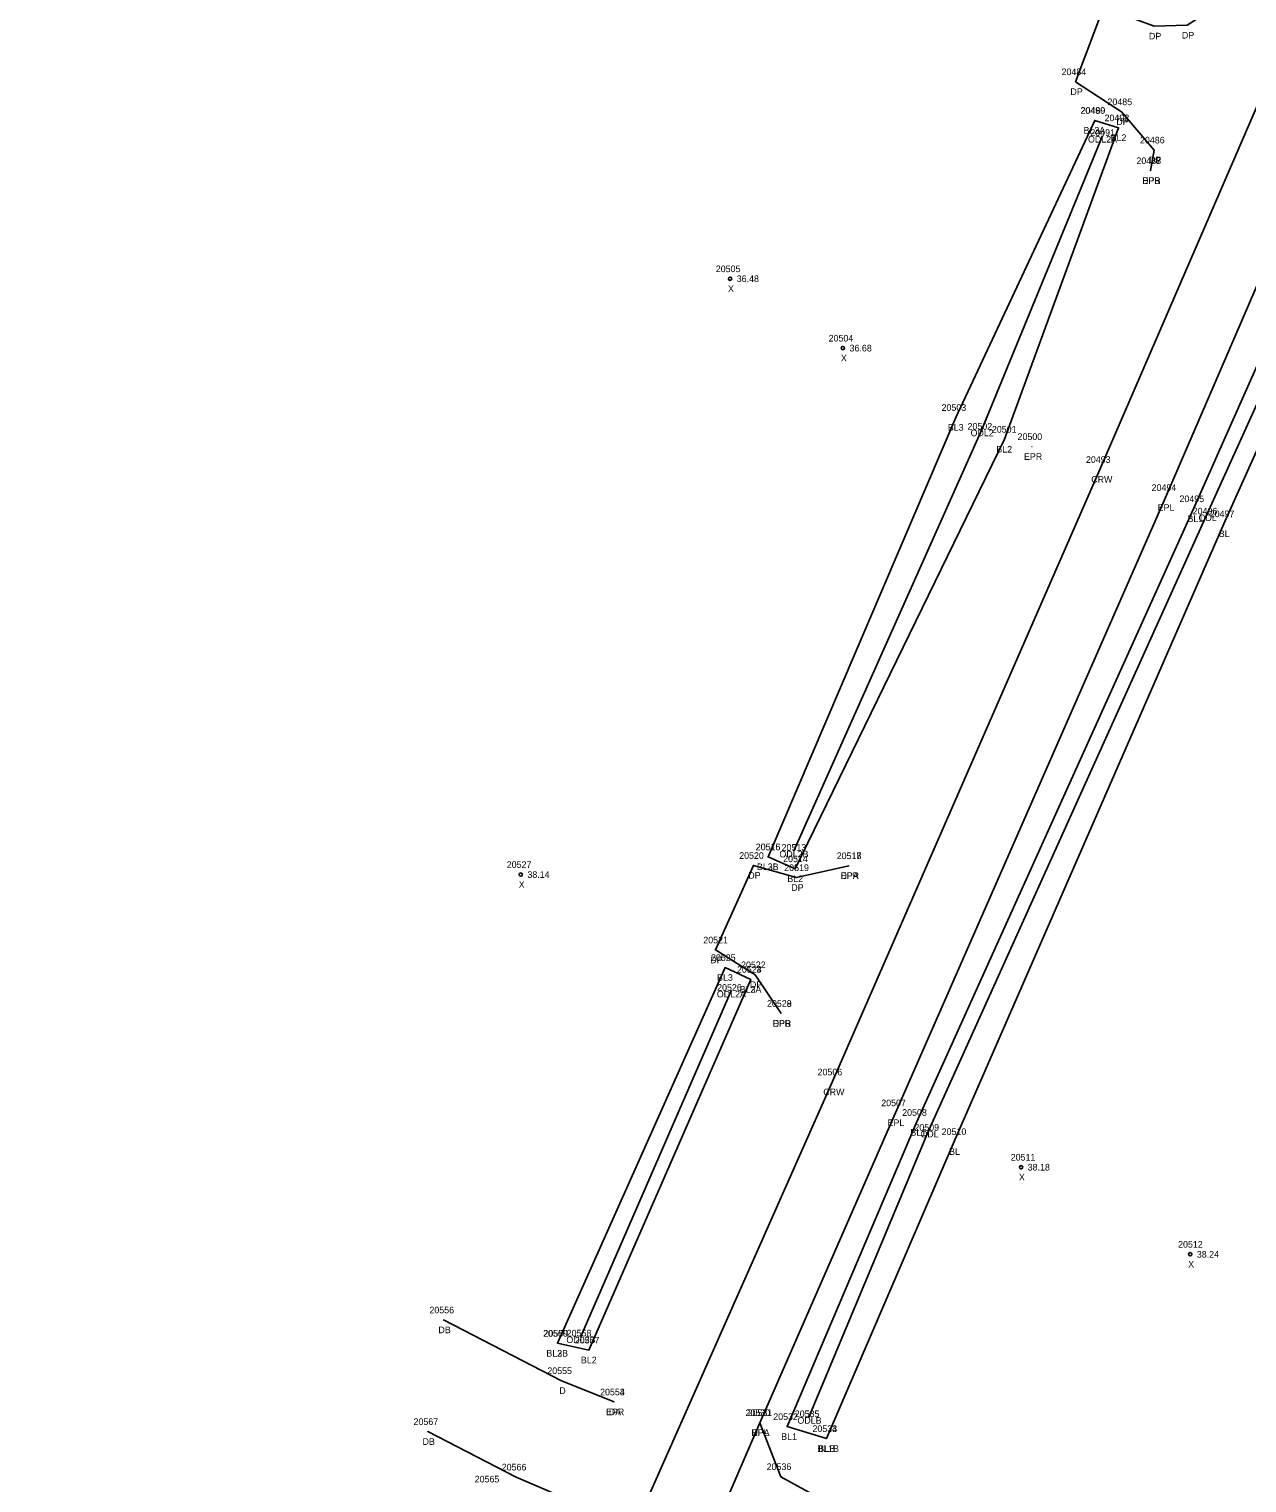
# Model space of a CAD drawing. Extents: x 2432729 to 2433340, y 684958 to 688103.
# Drawn here: x 2432777.1 to 2432960.9, y 685196.9 to 685416.3 of the extents above; entities that cross this region are included whole.
import ezdxf

# ---------------------------------------------------------------- set-up
doc = ezdxf.new("R2010")
doc.units = 0
for name, color, linetype in [('RD_DTM_BkLn1', 7, 'Continuous'), ('RD_EX_Driveway', 7, 'Continuous'), ('RD_EX_Driveway_txCode', 7, 'Continuous'), ('RD_EX_H2O', 7, 'Continuous'), ('RD_EX_H2O_txCode', 7, 'Continuous'), ('RD_EX_Road', 7, 'Continuous'), ('RD_EX_Road_txCode', 7, 'Continuous'), ('RD_Sketch8', 7, 'Continuous'), ('RD_SMD_Locator', 7, 'Continuous'), ('RD_SMD_Misc', 7, 'Continuous')]:
    doc.layers.add(name, color=color, linetype=linetype)

msp = doc.modelspace()

# ---------------------------------------------------------------- linework, layer by layer
at = {"layer": 'RD_DTM_BkLn1'}
for points in [[(2433067.41, 685690.62), (2433052.49, 685638.4), (2433035.04, 685585.7), (2433018.41, 685541.16), (2432999.85, 685493.3), (2432978.77, 685442.62), (2432938.71, 685349.86), (2432898.27, 685257.39), (2432861.69, 685174.74), (2432859.51, 685169.85), (2432818.13, 685076.09), (2432777.09, 684983.43)], [(2433087.86, 685684.95), (2433070.24, 685632.97), (2433050.83, 685581.32), (2433032.43, 685535.6), (2433015.06, 685486.22), (2432993.56, 685435.75), (2432952.83, 685343.93), (2432911.02, 685251.28), (2432891.52, 685205.36), (2432897.43, 685203.55)], [(2433102.05, 685679.62), (2433079.53, 685630.77), (2433059.07, 685578.75), (2433039.78, 685531.36), (2433020.13, 685482.85), (2432998.25, 685432.63), (2432957.4, 685341.66), (2432916.69, 685248.39), (2432897.43, 685203.55)], [(2432937.92, 685402.56), (2432941.52, 685401.44), (2432924.28, 685354.42), (2432892.73, 685289.58), (2432888.61, 685291.38)], [(2432937.92, 685402.56), (2432916.96, 685357.71), (2432888.61, 685291.38)], [(2432886.04, 685272.88), (2432882.12, 685274.67), (2432856.84, 685217.94)], [(2432886.04, 685272.88), (2432861.57, 685216.92), (2432856.84, 685217.94)]]:
    msp.add_lwpolyline(points, dxfattribs=at)
at = {"layer": 'RD_EX_Driveway'}
for points in [[(2432957.98, 685420.84), (2432951.85, 685416.92), (2432946.88, 685416.78), (2432939.23, 685419.58), (2432935.03, 685408.39), (2432941.96, 685403.86), (2432946.89, 685398.08), (2432946.33, 685394.97)], [(2432900.81, 685290.04), (2432892.9, 685288.24), (2432886.42, 685290.08), (2432880.67, 685277.32), (2432886.66, 685273.58), (2432890.58, 685267.74)], [(2432865.39, 685209.09), (2432857.42, 685212.3), (2432839.65, 685221.47)], [(2432887.37, 685205.96), (2432890.55, 685197.81), (2432896.21, 685194.66), (2432887.83, 685175.72), (2432878.57, 685173.71), (2432872.08, 685170.45)], [(2432858.68, 685194.25), (2432850.59, 685197.75), (2432837.25, 685204.61)]]:
    msp.add_lwpolyline(points, dxfattribs=at)
at = {"layer": 'RD_EX_H2O'}
msp.add_line((2432883.07, 685271.16), (2432860.35, 685218.98), dxfattribs=at)
for points in [[(2433091.72, 685683.25), (2433072.97, 685632.18), (2433053.46, 685580.43), (2433036.38, 685533.4), (2433017.44, 685484.85), (2432996.16, 685434.2), (2432954.84, 685343.07), (2432912.85, 685250.04), (2432894.77, 685206.8)], [(2432939.08, 685400.22), (2432920.88, 685355.88), (2432892.5, 685292.3)]]:
    msp.add_lwpolyline(points, dxfattribs=at)
at = {"layer": 'RD_EX_Road'}
msp.add_lwpolyline([(2433077.66, 685687.92), (2433062.23, 685635.7), (2433044.84, 685582.68), (2433028.22, 685537.07), (2433009.68, 685489.83), (2432988.53, 685438.27), (2432948.62, 685345.62), (2432907.86, 685252.74), (2432887.37, 685205.96), (2432872.08, 685170.45), (2432827.85, 685071.69), (2432787.31, 684979.59)], dxfattribs=at)
at = {"layer": 'RD_SMD_Locator'}
for centre, radius in [((2432935.03, 685408.39), 0.001), ((2432941.96, 685403.86), 0.001), ((2432937.92, 685402.56), 0.001), ((2432937.92, 685402.56), 0.001), ((2432941.52, 685401.44), 0.001), ((2432939.08, 685400.22), 0.001), ((2432946.89, 685398.08), 0.001), ((2432946.33, 685394.97), 0.001), ((2432946.33, 685394.97), 0.001), ((2432882.89, 685378.65), 0.25), ((2432899.92, 685368.18), 0.25), ((2432916.96, 685357.71), 0.001), ((2432920.88, 685355.88), 0.001), ((2432924.28, 685354.42), 0.001), ((2432928.47, 685353.31), 0.001), ((2432938.71, 685349.86), 0.001), ((2432948.62, 685345.62), 0.001), ((2432952.83, 685343.93), 0.001), ((2432954.84, 685343.07), 0.001), ((2432957.4, 685341.66), 0.001), ((2432888.61, 685291.38), 0.001), ((2432888.61, 685291.38), 0.001), ((2432892.5, 685292.3), 0.001), ((2432851.3, 685288.71), 0.25), ((2432886.42, 685290.08), 0.001), ((2432892.73, 685289.58), 0.001), ((2432900.81, 685290.04), 0.001), ((2432900.81, 685290.04), 0.001), ((2432892.9, 685288.24), 0.001), ((2432880.67, 685277.32), 0.001), ((2432882.12, 685274.67), 0.001), ((2432886.66, 685273.58), 0.001), ((2432883.07, 685271.16), 0.001), ((2432886.04, 685272.88), 0.001), ((2432886.04, 685272.88), 0.001), ((2432890.58, 685267.74), 0.001), ((2432890.58, 685267.74), 0.001), ((2432898.27, 685257.39), 0.001), ((2432907.86, 685252.74), 0.001), ((2432911.02, 685251.28), 0.001), ((2432912.85, 685250.04), 0.001), ((2432916.69, 685248.39), 0.001), ((2432926.8, 685244.53), 0.25), ((2432952.33, 685231.38), 0.25), ((2432839.65, 685221.47), 0.001), ((2432860.35, 685218.98), 0.001), ((2432856.84, 685217.94), 0.001), ((2432856.84, 685217.94), 0.001), ((2432861.57, 685216.92), 0.001), ((2432857.42, 685212.3), 0.001), ((2432865.39, 685209.09), 0.001), ((2432865.39, 685209.09), 0.001), ((2432887.37, 685205.96), 0.001), ((2432887.37, 685205.96), 0.001), ((2432891.52, 685205.36), 0.001), ((2432894.77, 685206.8), 0.001), ((2432837.25, 685204.61), 0.001), ((2432897.43, 685203.55), 0.001), ((2432897.43, 685203.55), 0.001), ((2432850.59, 685197.75), 0.001), ((2432890.55, 685197.81), 0.001)]:
    msp.add_circle(centre, radius, dxfattribs=at)

# ---------------------------------------------------------------- texts
at = {"layer": 'RD_EX_Driveway_txCode'}
for s, p in [('DP', (2432951.07, 685414.92)), ('DP', (2432946.1, 685414.78)), ('20484', (2432932.91, 685409.39)), ('DP', (2432934.25, 685406.39)), ('20485', (2432939.84, 685404.86)), ('DP', (2432941.18, 685401.86)), ('20486', (2432944.75, 685399.08)), ('20487', (2432944.21, 685395.97)), ('DP', (2432946.11, 685396.08)), ('DPB', (2432945.08, 685392.97)), ('20520', (2432884.26, 685291.08)), ('20518', (2432898.98, 685291.04)), ('DP', (2432885.64, 685288.08)), ('20519', (2432891.06, 685289.24)), ('DPA', (2432899.55, 685288.04)), ('DP', (2432892.12, 685286.24)), ('20521', (2432878.84, 685278.32)), ('DP', (2432879.89, 685275.32)), ('20522', (2432884.54, 685274.58)), ('DP', (2432885.88, 685271.58)), ('20528', (2432888.46, 685268.74)), ('DPB', (2432889.32, 685265.74)), ('20556', (2432837.51, 685222.47)), ('DB', (2432838.87, 685219.47)), ('20555', (2432855.3, 685213.3)), ('D', (2432857.11, 685210.3)), ('20554', (2432863.27, 685210.09)), ('DA', (2432864.59, 685207.09)), ('20531', (2432885.53, 685206.96)), ('20567', (2432835.11, 685205.61)), ('DB', (2432836.47, 685202.61)), ('DPA', (2432886.1, 685203.96)), ('20566', (2432848.42, 685198.75)), ('20536', (2432888.41, 685198.81))]:
    msp.add_text(s, height=1, dxfattribs=at).set_placement(p)
at = {"layer": 'RD_EX_H2O_txCode'}
for s, p in [('20491', (2432937.25, 685400.22)), ('ODL2A', (2432936.9, 685399.22)), ('20502', (2432918.72, 685355.88)), ('ODL2', (2432919.18, 685354.88)), ('20496', (2432952.7, 685343.07)), ('ODL', (2432953.59, 685342.07)), ('20513', (2432890.66, 685292.3)), ('ODL2B', (2432890.33, 685291.3)), ('ODL2A', (2432880.89, 685270.16)), ('20526', (2432880.93, 685271.16)), ('20509', (2432910.7, 685250.04)), ('ODL', (2432911.61, 685249.04)), ('ODL2B', (2432858.18, 685217.98)), ('20558', (2432858.23, 685218.98)), ('20535', (2432892.65, 685206.8)), ('ODLB', (2432893.05, 685205.8))]:
    msp.add_text(s, height=1, dxfattribs=at).set_placement(p)
at = {"layer": 'RD_EX_Road_txCode'}
for s, p in [('20488', (2432944.21, 685395.97)), ('EPR', (2432945.1, 685392.97)), ('20500', (2432926.27, 685354.31)), ('EPR', (2432927.24, 685351.31)), ('20494', (2432946.5, 685346.62)), ('EPL', (2432947.41, 685343.62)), ('20517', (2432898.98, 685291.04)), ('EPR', (2432899.59, 685288.04)), ('20529', (2432888.46, 685268.74)), ('EPR', (2432889.35, 685265.74)), ('20507', (2432905.7, 685253.74)), ('EPL', (2432906.65, 685250.74)), ('20553', (2432863.27, 685210.09)), ('EPR', (2432864.16, 685207.09)), ('20530', (2432885.21, 685206.96)), ('EPL', (2432886.16, 685203.96))]:
    msp.add_text(s, height=1, dxfattribs=at).set_placement(p)
at = {"layer": 'RD_Sketch8'}
for s, p in [('20505', (2432880.73, 685379.65)), ('36.48', (2432883.89, 685378.15)), ('X', (2432882.57, 685376.65)), ('20504', (2432897.76, 685369.18)), ('36.68', (2432900.92, 685367.68)), ('X', (2432899.61, 685366.18)), ('20527', (2432849.18, 685289.71)), ('38.14', (2432852.3, 685288.21)), ('X', (2432850.98, 685286.71)), ('20511', (2432925.24, 685245.53)), ('38.18', (2432927.8, 685244.03)), ('X', (2432926.48, 685242.53)), ('20512', (2432950.5, 685232.38)), ('38.24', (2432953.33, 685230.88)), ('X', (2432952.02, 685229.38))]:
    msp.add_text(s, height=1, dxfattribs=at).set_placement(p)
at = {"layer": 'RD_SMD_Misc'}
for s, p in [('20490', (2432935.76, 685403.56)), ('20489', (2432935.8, 685403.56)), ('20492', (2432939.4, 685402.44)), ('BL3A', (2432936.23, 685400.56)), ('BL2A', (2432936.23, 685400.56)), ('BL2', (2432940.32, 685399.44)), ('20503', (2432914.8, 685358.71)), ('BL3', (2432915.75, 685355.71)), ('20501', (2432922.4, 685355.42)), ('BL2', (2432923.07, 685352.42)), ('20493', (2432936.59, 685350.86)), ('CRW', (2432937.39, 685347.86)), ('20495', (2432950.71, 685344.93)), ('20497', (2432955.28, 685342.66)), ('BL1', (2432951.91, 685341.93)), ('BL', (2432956.64, 685339.66)), ('20516', (2432886.75, 685292.38)), ('20515', (2432886.77, 685292.38)), ('20514', (2432890.89, 685290.58)), ('BL2B', (2432886.93, 685289.38)), ('BL3B', (2432886.93, 685289.38)), ('BL2', (2432891.52, 685287.58)), ('20525', (2432880, 685275.67)), ('BL3', (2432880.92, 685272.67)), ('20523', (2432883.92, 685273.88)), ('20524', (2432883.92, 685273.88)), ('BL2A', (2432884.34, 685270.88)), ('BL3A', (2432884.34, 685270.88)), ('20506', (2432896.09, 685258.39)), ('CRW', (2432896.95, 685255.39)), ('20508', (2432908.86, 685252.28)), ('BL1', (2432910.1, 685249.28)), ('20510', (2432914.82, 685249.39)), ('BL', (2432915.94, 685246.39)), ('20560', (2432854.66, 685218.94)), ('20559', (2432854.72, 685218.94)), ('20557', (2432859.45, 685217.92)), ('BL2B', (2432855.16, 685215.94)), ('BL3B', (2432855.16, 685215.94)), ('BL2', (2432860.37, 685214.92)), ('20532', (2432889.4, 685206.36)), ('20533', (2432895.32, 685204.55)), ('20534', (2432895.32, 685204.55)), ('BL1', (2432890.6, 685203.36)), ('BL1B', (2432896.04, 685201.55)), ('BLB', (2432896.2, 685201.55)), ('20565', (2432844.34, 685196.94))]:
    msp.add_text(s, height=1, dxfattribs=at).set_placement(p)

doc.saveas('drawing.dxf')
